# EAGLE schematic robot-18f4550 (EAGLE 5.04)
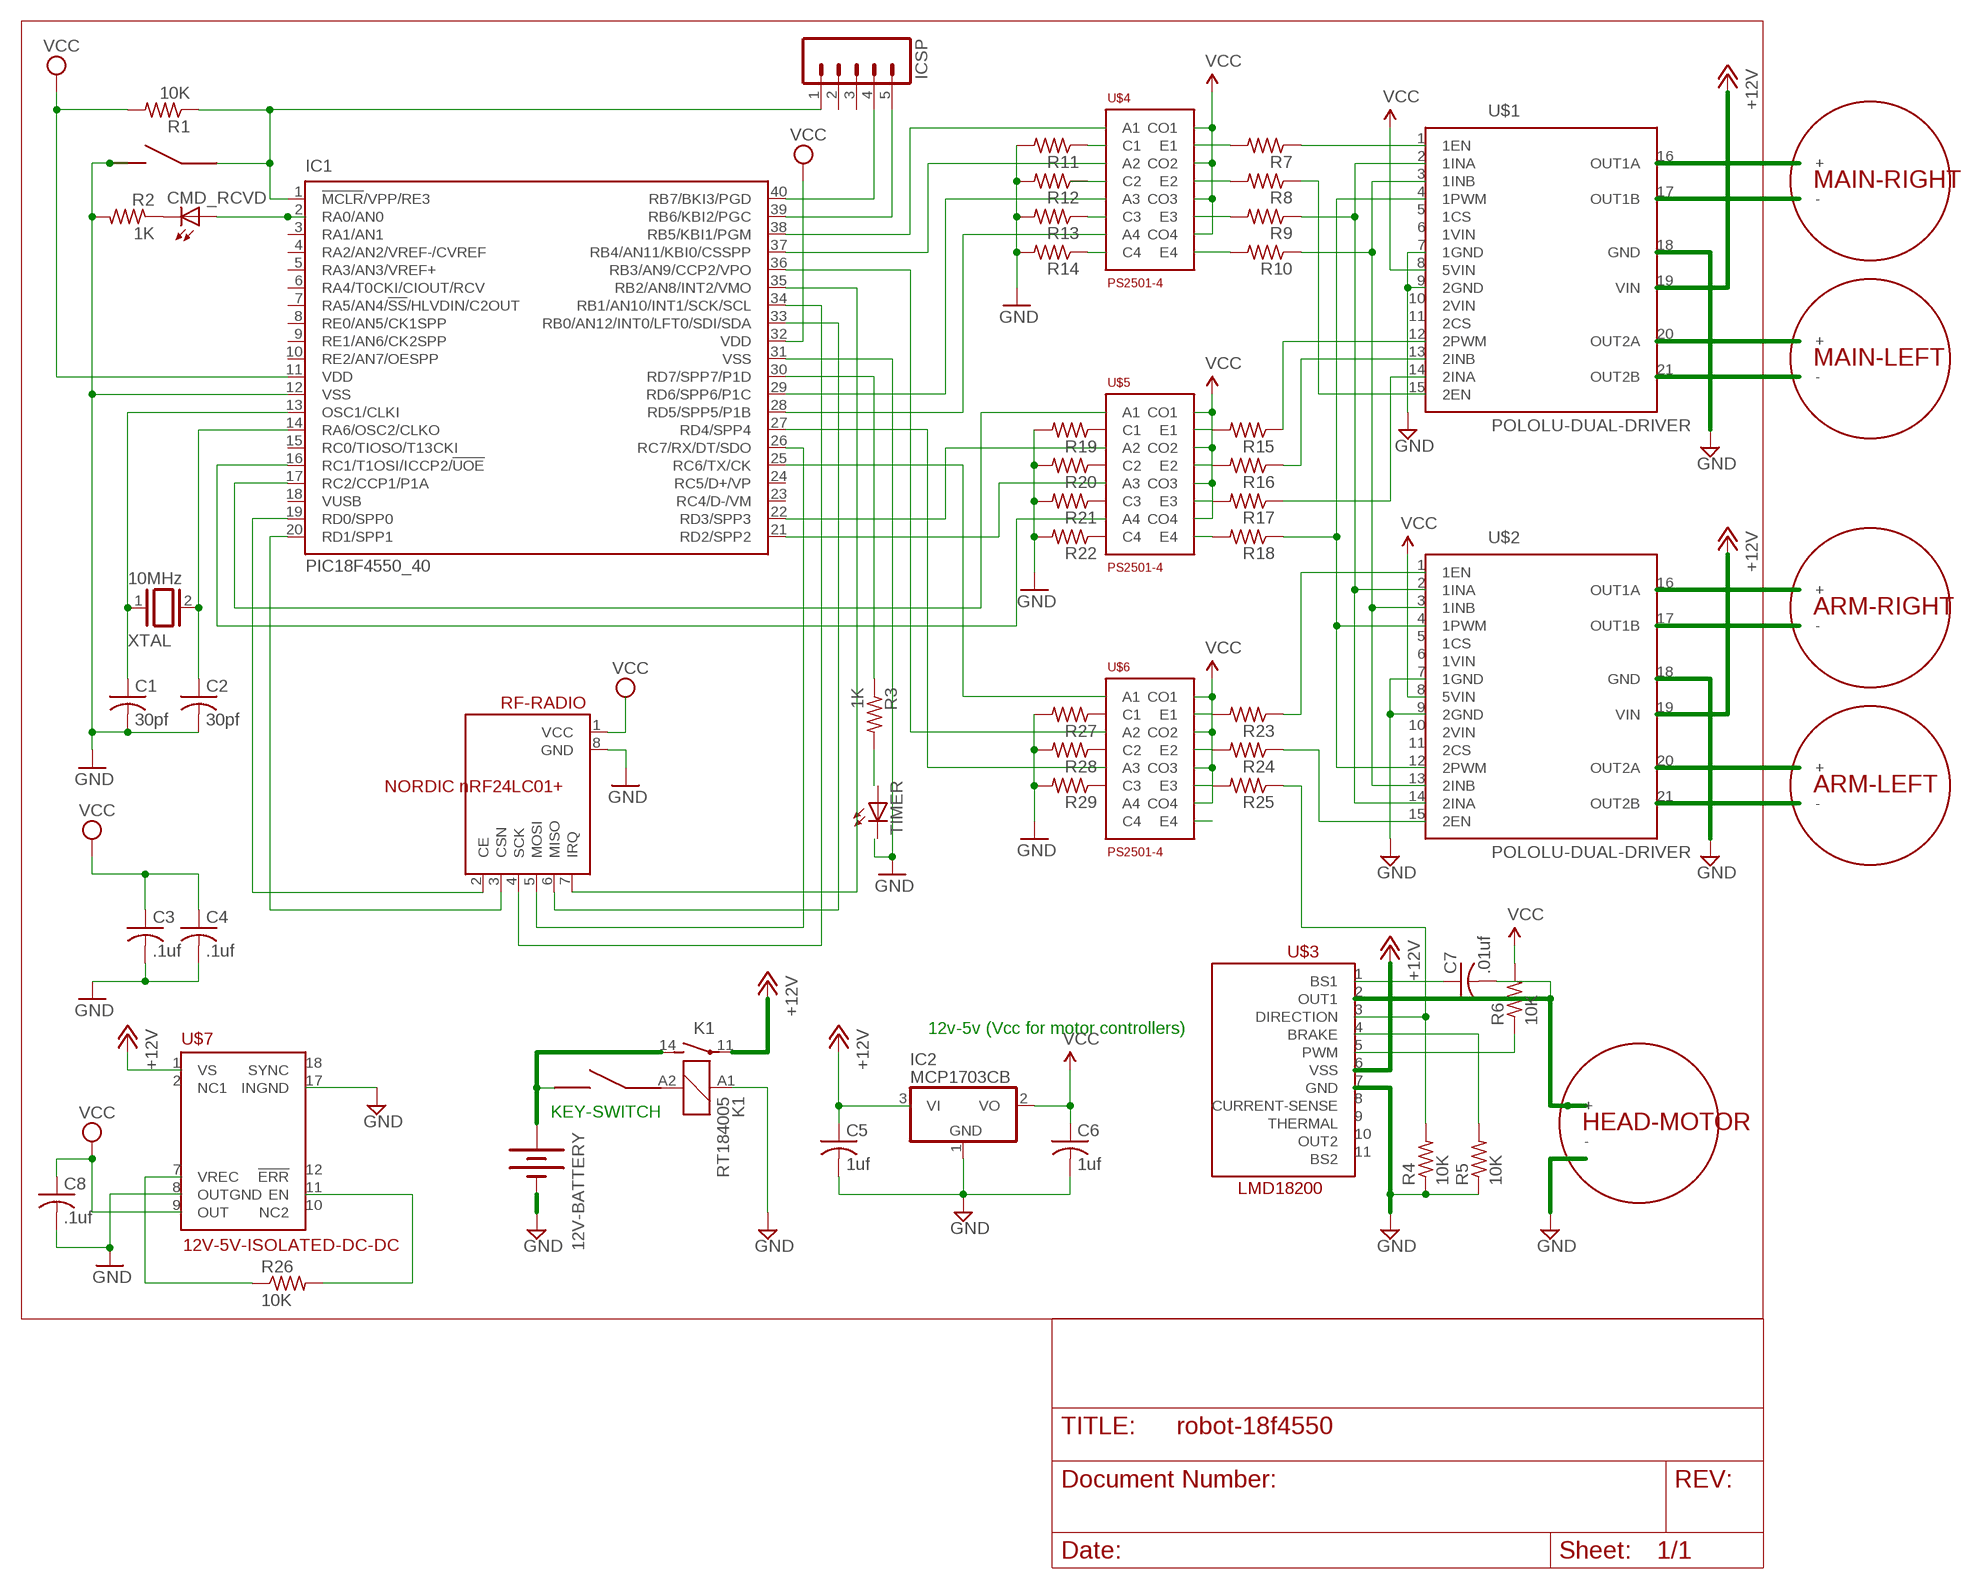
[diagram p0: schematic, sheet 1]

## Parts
12V-BATTERY  BATTERYAA  [BATTERY-AA]
ARM-LEFT  DC-MOTOR  [DC-MOTOR]
ARM-RIGHT  DC-MOTOR  [DC-MOTOR]
C1  30pf  C-US102-043X133  [C102-043X133]
C2  30pf  C-US102-043X133  [C102-043X133]
C3  .1uf  C-US102-043X133  [C102-043X133]
C4  .1uf  C-US102-043X133  [C102-043X133]
C5  1uf  C-US102-043X133  [C102-043X133]
C6  1uf  C-US102-043X133  [C102-043X133]
C7  .01uf  C-US102-043X133  [C102-043X133]
C8  .1uf  C-US102-043X133  [C102-043X133]
CMD_RCVD  LEDCHIPLED_0603  [CHIPLED_0603]
HEAD-MOTOR  DC-MOTOR  [DC-MOTOR]
IC1  PIC18F4550_40  [DIL40]
IC2  MCP1703CB  [SOT23]
ICSP  M05  [05P]
K1  RT184005  [RT-N/O12A3.5]
KEY-SWITCH  KEY-SWITCH  PUSH-BUTTON-SWITCH  [2SIL]
MAIN-LEFT  DC-MOTOR  [DC-MOTOR]
MAIN-RIGHT  DC-MOTOR  [DC-MOTOR]
R1  10K  R-US_0617/22  [0617/22]
R2  1K  R-US_0617/22  [0617/22]
R3  1K  R-US_0617/22  [0617/22]
R4  10K  R-US_0617/22  [0617/22]
R5  10K  R-US_0617/22  [0617/22]
R6  10K  R-US_0617/22  [0617/22]
R7  R-US_0617/22  [0617/22]
R8  R-US_0617/22  [0617/22]
R9  R-US_0617/22  [0617/22]
R10  R-US_0617/22  [0617/22]
R11  R-US_0617/22  [0617/22]
R12  R-US_0617/22  [0617/22]
R13  R-US_0617/22  [0617/22]
R14  R-US_0617/22  [0617/22]
R15  R-US_0617/22  [0617/22]
R16  R-US_0617/22  [0617/22]
R17  R-US_0617/22  [0617/22]
R18  R-US_0617/22  [0617/22]
R19  R-US_0617/22  [0617/22]
R20  R-US_0617/22  [0617/22]
R21  R-US_0617/22  [0617/22]
R22  R-US_0617/22  [0617/22]
R23  R-US_0617/22  [0617/22]
R24  R-US_0617/22  [0617/22]
R25  R-US_0617/22  [0617/22]
R26  10K  R-US_0617/22  [0617/22]
R27  R-US_0617/22  [0617/22]
R28  R-US_0617/22  [0617/22]
R29  R-US_0617/22  [0617/22]
RESET  PUSH-BUTTON-SWITCH  [2SIL]
RF-RADIO  NORDIC nRF24LC01+  NORDIC-BREAKOUT  [8SIL]
TIMER  LEDCHIPLED_0603  [CHIPLED_0603]
U$1  POLOLU-DUAL-DRIVER  [POLOLU-DUAL-DRIVER]
U$2  POLOLU-DUAL-DRIVER  [POLOLU-DUAL-DRIVER]
U$3  LMD18200  [11SIL]
U$4  PS2501-4  [16DIP]
U$5  PS2501-4  [16DIP]
U$6  PS2501-4  [16DIP]
U$7  12V-5V-ISOLATED-DC-DC  [18DIL]
XTAL  10MHz  XTAL  [Q]

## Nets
+12V: C5.1 IC2.3(VI) K1.11(2:P) U$1.19(VIN) U$2.19(VIN) U$3.6(VSS) U$7.1(VS)
GND: 12V-BATTERY.GND@1(-) C1.2 C2.2 C3.2 C4.2 C5.2 C6.2 C8.2 IC1.12(VSS) IC1.31(VSS) IC2.1(GND) K1.A1 R2.2 R4.1 R5.1 R11.2 R12.2 R13.2 R14.2 R19.2 R20.2 R21.2 R22.2 R27.2 R28.2 R29.2 RESET.COM RF-RADIO.8(GND) U$1.7(1GND) U$1.9(2GND) U$1.18(GND) U$2.7(1GND) U$2.9(2GND) U$2.18(GND) U$3.7(GND) U$7.8(OUTGND) U$7.17(INGND)
N$1: CMD_RCVD.C R2.1
N$2: CMD_RCVD.A IC1.2(RA0/AN0)
N$3: MAIN-RIGHT.P$2(-) U$1.17(OUT1B)
N$4: MAIN-RIGHT.P$1(+) U$1.16(OUT1A)
N$6: IC1.39(RB6/KBI2/PGC) ICSP.5
N$8: MAIN-LEFT.P$1(+) U$1.20(OUT2A)
N$9: C1.1 IC1.13(OSC1/CLKI) XTAL.1
N$10: C2.1 IC1.14(RA6/OSC2/CLKO) XTAL.2
N$11: IC1.19(RD0/SPP0) RF-RADIO.2(CE)
N$12: IC1.16(RC1/T1OSI/ICCP2/!UOE) U$5.P$7(A4)
N$13: IC1.17(RC2/CCP1/P1A) U$5.P$1(A1)
N$14: MAIN-LEFT.P$2(-) U$1.21(OUT2B)
N$15: IC1.25(RC6/TX/CK) U$6.P$1(A1)
N$16: IC1.33(RB0/AN12/INT0/LFT0/SDI/SDA) RF-RADIO.6(MISO)
N$17: IC1.20(RD1/SPP1) RF-RADIO.3(CSN)
N$18: IC1.29(RD6/SPP6/P1C) U$4.P$5(A3)
N$19: R3.2
N$20: IC1.26(RC7/RX/DT/SDO) RF-RADIO.5(MOSI)
N$21: IC1.34(RB1/AN10/INT1/SCK/SCL) RF-RADIO.4(SCK)
N$22: IC1.35(RB2/AN8/INT2/VMO) RF-RADIO.7(IRQ)
N$23: IC1.21(RD2/SPP2) U$5.P$5(A3)
N$24: IC1.37(RB4/AN11/KBI0/CSSPP) U$4.P$3(A2)
N$25: IC1.22(RD3/SPP3) U$5.P$3(A2)
N$26: R10.1 U$1.3(1INB) U$2.3(1INB) U$2.13(2INB)
N$27: R9.1 U$1.2(1INA) U$2.2(1INA) U$2.14(2INA)
N$28: IC1.1(!MCLR!/VPP/RE3) ICSP.1 R1.1 RESET.NO
N$29: K1.A2 KEY-SWITCH.NO
N$30: 12V-BATTERY.PWR@1(+) K1.14(2:S) KEY-SWITCH.COM
N$31: IC1.38(RB5/KBI1/PGM) U$4.P$1(A1)
N$32: C7.1 U$3.1(BS1)
N$33: IC1.27(RD4/SPP4) U$6.P$5(A3)
N$34: R5.2 U$3.4(BRAKE)
N$35: R7.1 U$1.1(1EN)
N$37: C7.2 HEAD-MOTOR.P$1(+) U$3.2(OUT1)
N$38: ARM-LEFT.P$1(+) U$2.20(OUT2A)
N$39: ARM-LEFT.P$2(-) U$2.21(OUT2B)
N$40: ARM-RIGHT.P$2(-) U$2.17(OUT1B)
N$41: ARM-RIGHT.P$1(+) U$2.16(OUT1A)
N$42: IC1.36(RB3/AN9/CCP2/VPO) U$6.P$3(A2)
N$43: R10.2 U$4.P$9(E4)
N$44: R6.1 U$3.5(PWM)
N$45: R7.2 U$4.P$15(E1)
N$46: R9.2 U$4.P$11(E3)
N$47: R8.2 U$4.P$13(E2)
N$48: R11.1 U$4.P$2(C1)
N$49: U$4.P$4(C2)
N$50: R13.1 U$4.P$6(C3)
N$51: R14.1 U$4.P$8(C4)
N$52: IC1.30(RD7/SPP7/P1D) R3.1
N$53: R17.1 U$1.14(2INA)
N$54: IC1.28(RD5/SPP5/P1B) U$4.P$7(A4)
N$55: R8.1 U$1.15(2EN)
N$56: R16.1 U$1.13(2INB)
N$57: R15.2 U$5.P$15(E1)
N$58: R18.2 U$5.P$9(E4)
N$59: R17.2 U$5.P$11(E3)
N$60: R16.2 U$5.P$13(E2)
N$61: R19.1 U$5.P$2(C1)
N$62: R20.1 U$5.P$4(C2)
N$63: R21.1 U$5.P$6(C3)
N$64: R22.1 U$5.P$8(C4)
N$65: R15.1 U$1.12(2PWM)
N$66: R24.1 U$2.15(2EN)
N$67: R23.1 U$2.1(1EN)
N$68: IC1.40(RB7/BKI3/PGD) ICSP.4
N$69: R4.2 R25.1 U$3.3(DIRECTION)
N$70: R18.1 U$1.4(1PWM) U$2.4(1PWM) U$2.12(2PWM)
N$71: R23.2 U$6.P$15(E1)
N$72: U$6.P$9(E4)
N$73: R25.2 U$6.P$11(E3)
N$74: R24.2 U$6.P$13(E2)
N$75: R27.1 U$6.P$2(C1)
N$76: R28.1 U$6.P$4(C2)
N$77: R29.1 U$6.P$6(C3)
N$80: R26.2 U$7.11(EN)
N$81: R26.1 U$7.7(VREC)
VCC: C3.1 C4.1 C6.1 C8.1 IC1.11(VDD) IC1.32(VDD) IC2.2(VO) R1.2 R6.2 RF-RADIO.1(VCC) U$1.8(5VIN) U$2.8(5VIN) U$4.P$10(CO4) U$4.P$12(CO3) U$4.P$14(CO2) U$4.P$16(CO1) U$5.P$10(CO4) U$5.P$12(CO3) U$5.P$14(CO2) U$5.P$16(CO1) U$6.P$10(CO4) U$6.P$12(CO3) U$6.P$14(CO2) U$6.P$16(CO1) U$7.9(OUT)
Unconnected: HEAD-MOTOR.P$2(-) IC1.3(RA1/AN1) IC1.4(RA2/AN2/VREF-/CVREF) IC1.5(RA3/AN3/VREF+) IC1.6(RA4/T0CKI/CIOUT/RCV) IC1.7(RA5/AN4/!SS!/HLVDIN/C2OUT) IC1.8(RE0/AN5/CK1SPP) IC1.9(RE1/AN6/CK2SPP) IC1.10(RE2/AN7/OESPP) IC1.15(RC0/TIOSO/T13CKI) IC1.18(VUSB) IC1.23(RC4/D-/VM) IC1.24(RC5/D+/VP) ICSP.2 ICSP.3 R12.1 TIMER.A TIMER.C U$1.5(1CS) U$1.6(1VIN) U$1.10(2VIN) U$1.11(2CS) U$2.5(1CS) U$2.6(1VIN) U$2.10(2VIN) U$2.11(2CS) U$3.8(CURRENT-SENSE) U$3.9(THERMAL) U$3.10(OUT2) U$3.11(BS2) U$6.P$7(A4) U$6.P$8(C4) U$7.2(NC1) U$7.10(NC2) U$7.12(!ERR) U$7.18(SYNC)

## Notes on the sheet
- 12v-5v (Vcc for motor controllers)
- KEY-SWITCH

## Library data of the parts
12V-BATTERY = SparkFun:BATTERY: Battery Holders
ARM-LEFT ARM-RIGHT HEAD-MOTOR MAIN-LEFT MAIN-RIGHT = trl:DC-MOTOR: DC Motor
C1-C8 = rcl:C-US: CAPACITOR, American symbol
CMD_RCVD TIMER = led:LED: LED
IC1 = microchip:PIC18F4*_40: USB Microcontrollers with nanoWatt Technology High-Performance, Enhanced Flash, 28/40/44-Pin, Source: http://ww1.microchip.com/downloads/en/devicedoc/39632c.pdf
IC2 = linear:MCP1703: 250 mA, 16V, Low Quiescent Current LDO Regulator Source: http://ww1.microchip.com/downloads/en/DeviceDoc/22049b.pdf
ICSP = con-amp-quick:M05: AMP QUICK CONNECTOR
K1 = relay:RT?*: Power PCB Relay SCHRACK 1 pole 12 / 16 A, DC- or AC-coil Source: http://www.schrack.com/.. 5819.pdf
KEY-SWITCH RESET = trl:PUSH-BUTTON-SWITCH
R1-R29 = resistor:R-US_: RESISTOR, American symbol
RF-RADIO = trl:NORDIC-BREAKOUT: Spark Fun Electronic's Nordic Semiconductor nRF24L01 with chip antenna
U$1 U$2 = trl:POLOLU-DUAL-DRIVER
U$3 = trl:LMD18200
U$4-U$6 = trl:PS2501-4
U$7 = trl:12V-5V-ISOLATED-DC-DC
XTAL = special:XTAL: CRYSTAL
